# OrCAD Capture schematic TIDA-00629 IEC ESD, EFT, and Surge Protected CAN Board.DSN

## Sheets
1 S01 COVER PAGE: note: 6591689; note: M. PEFFERS; note: KRYPTON SOLUTIONS
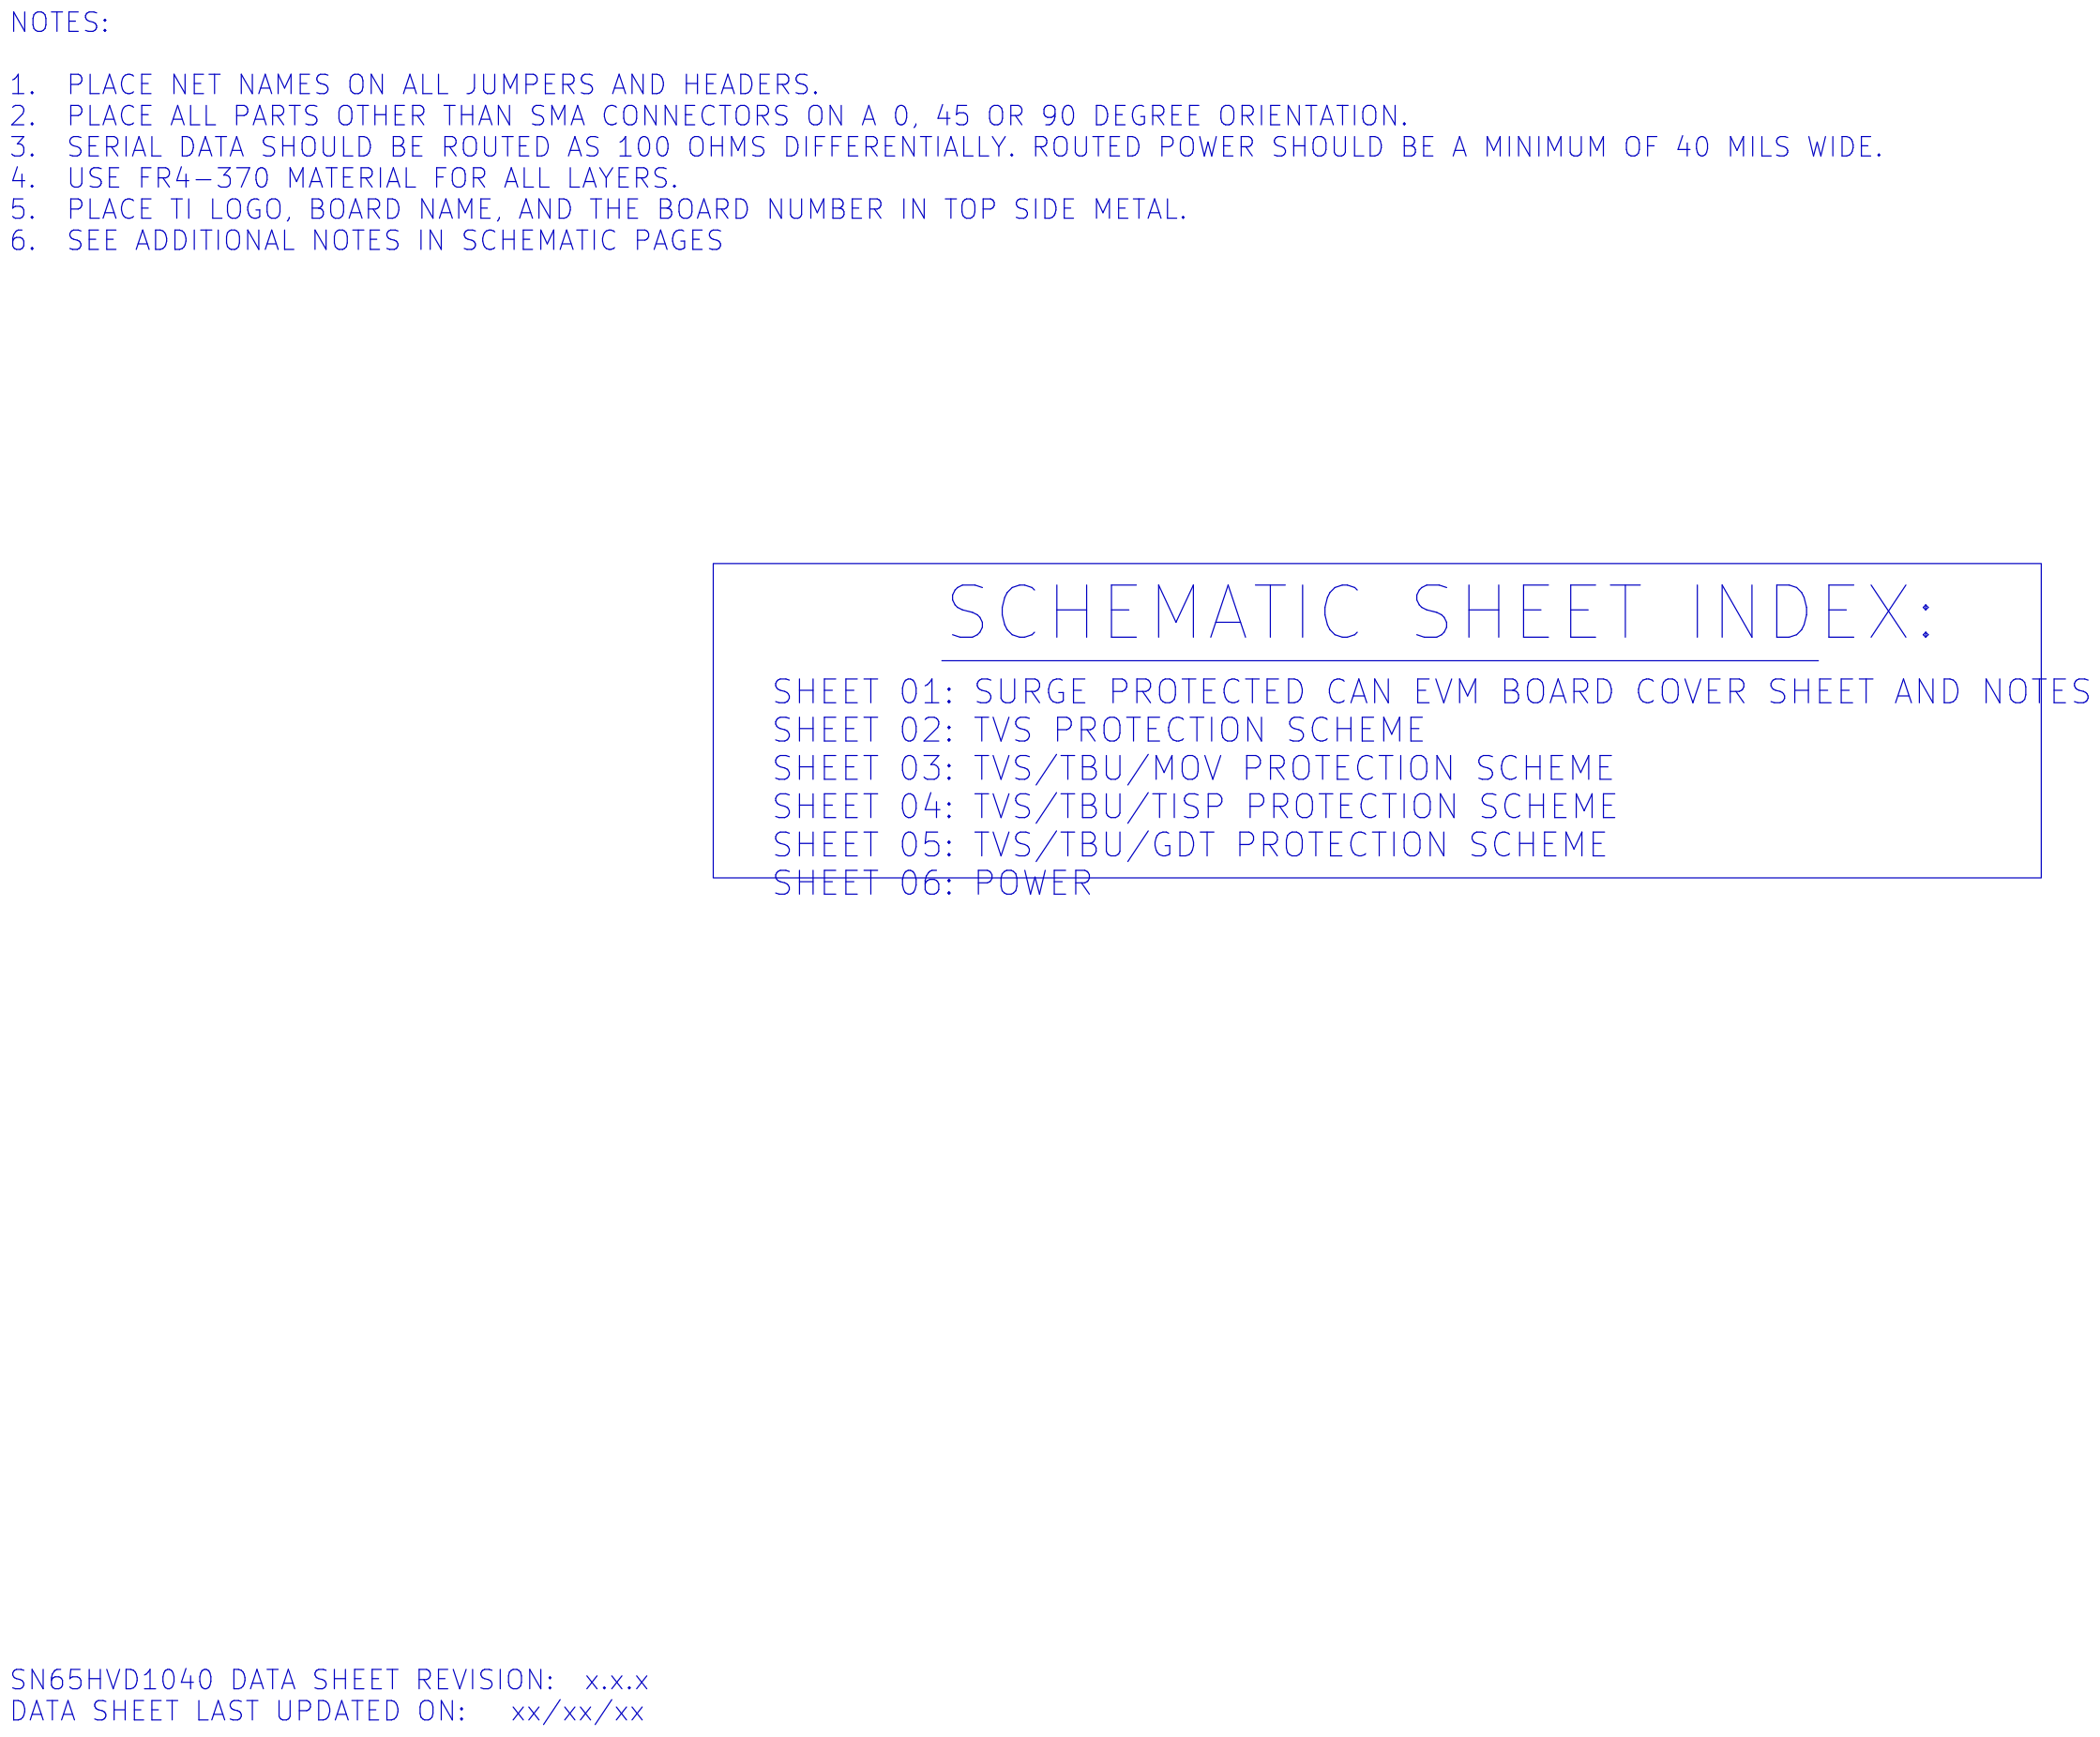
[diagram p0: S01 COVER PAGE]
2 S02 TVS PROTECTION: size B
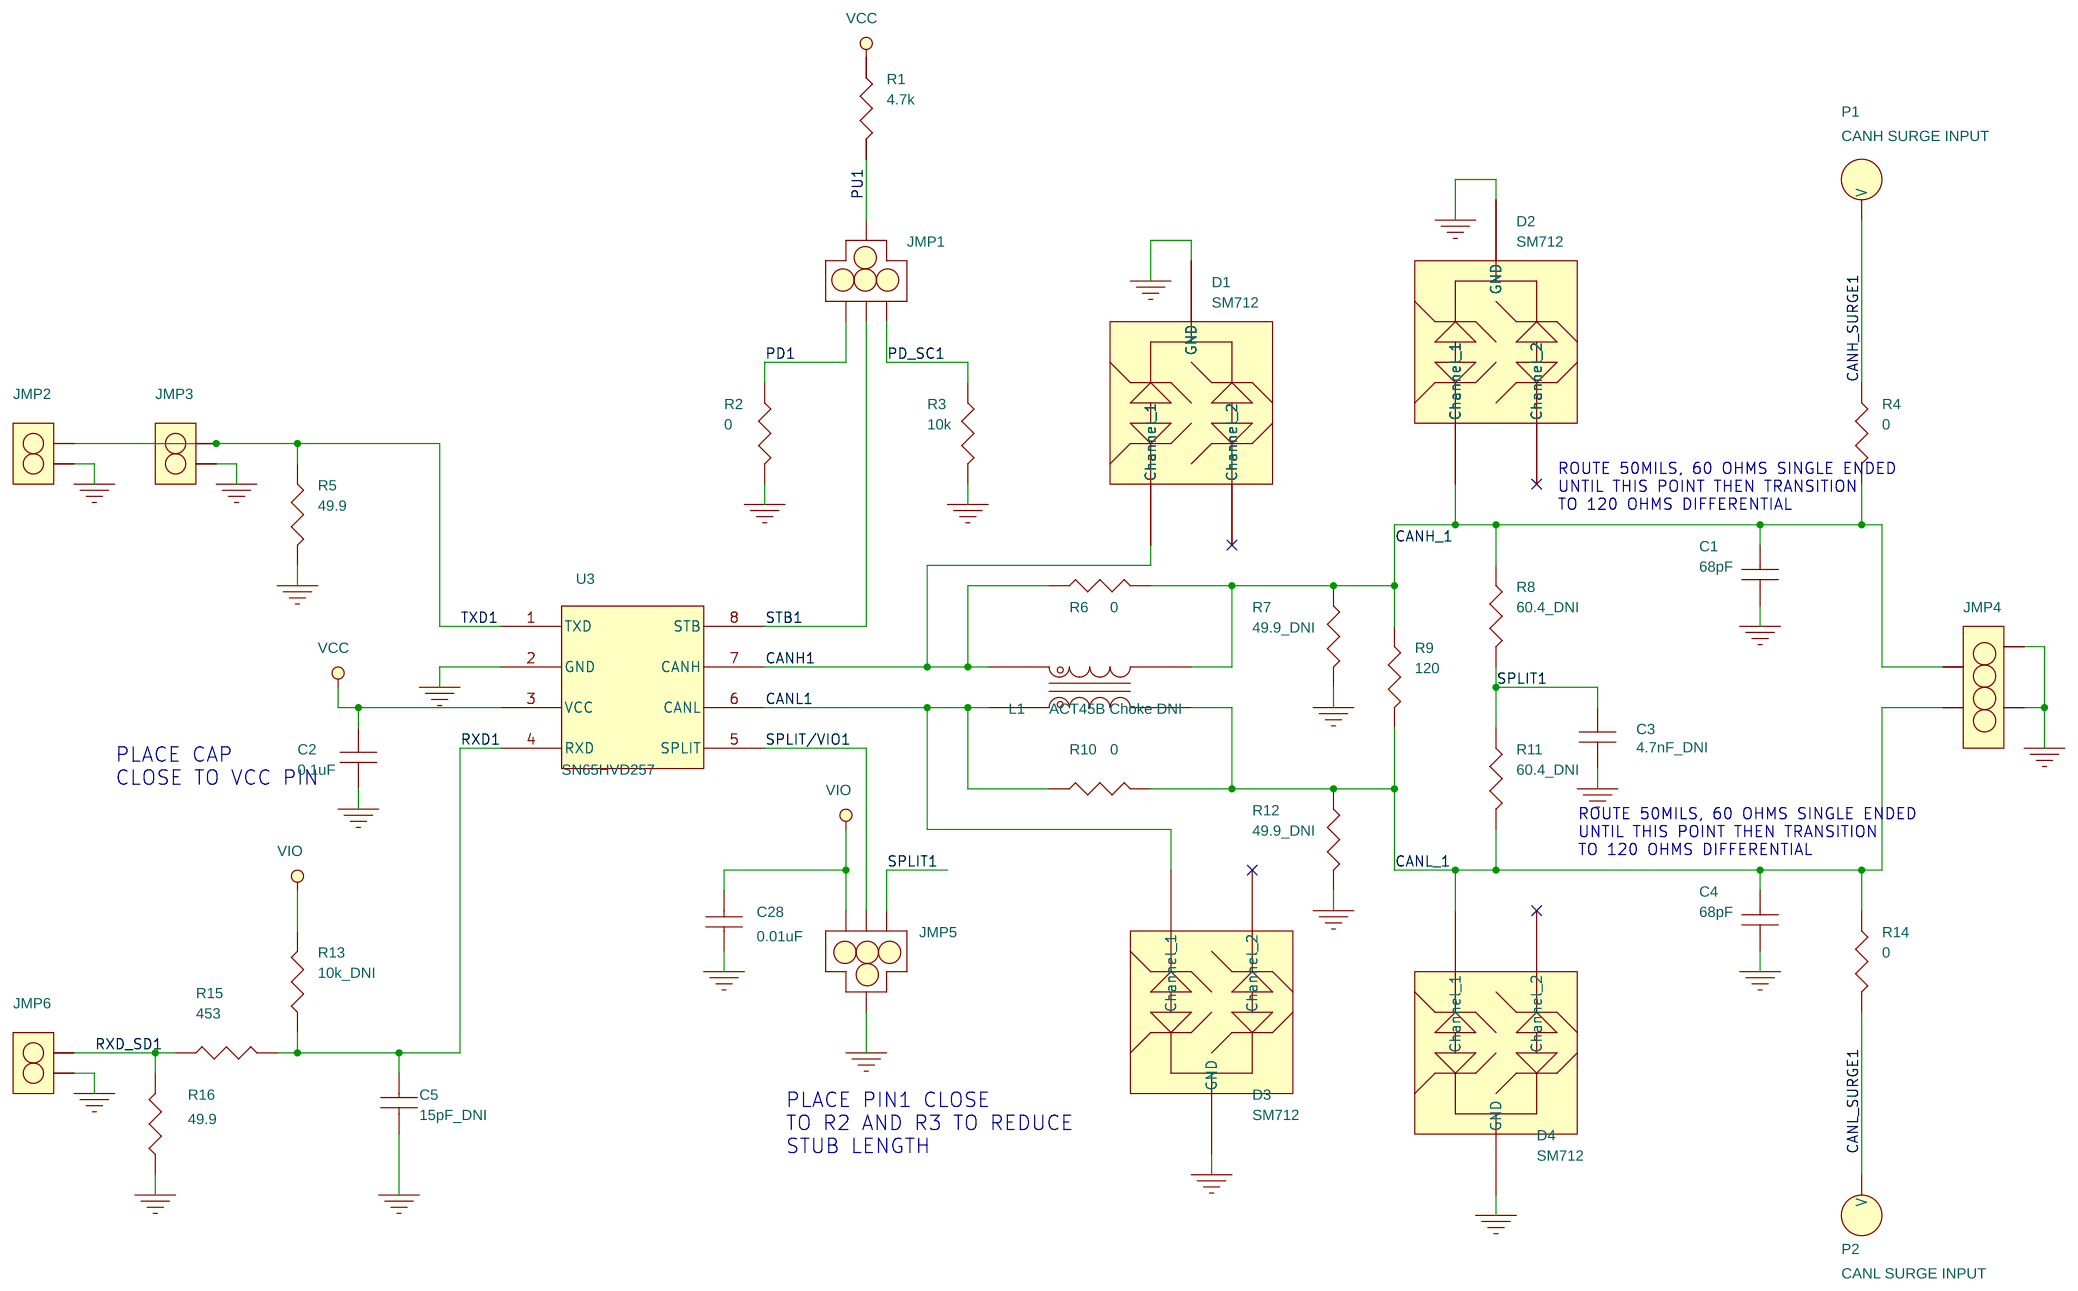
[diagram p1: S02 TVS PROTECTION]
3 S03 TVS, TBU, MOV PROTECTION: size B
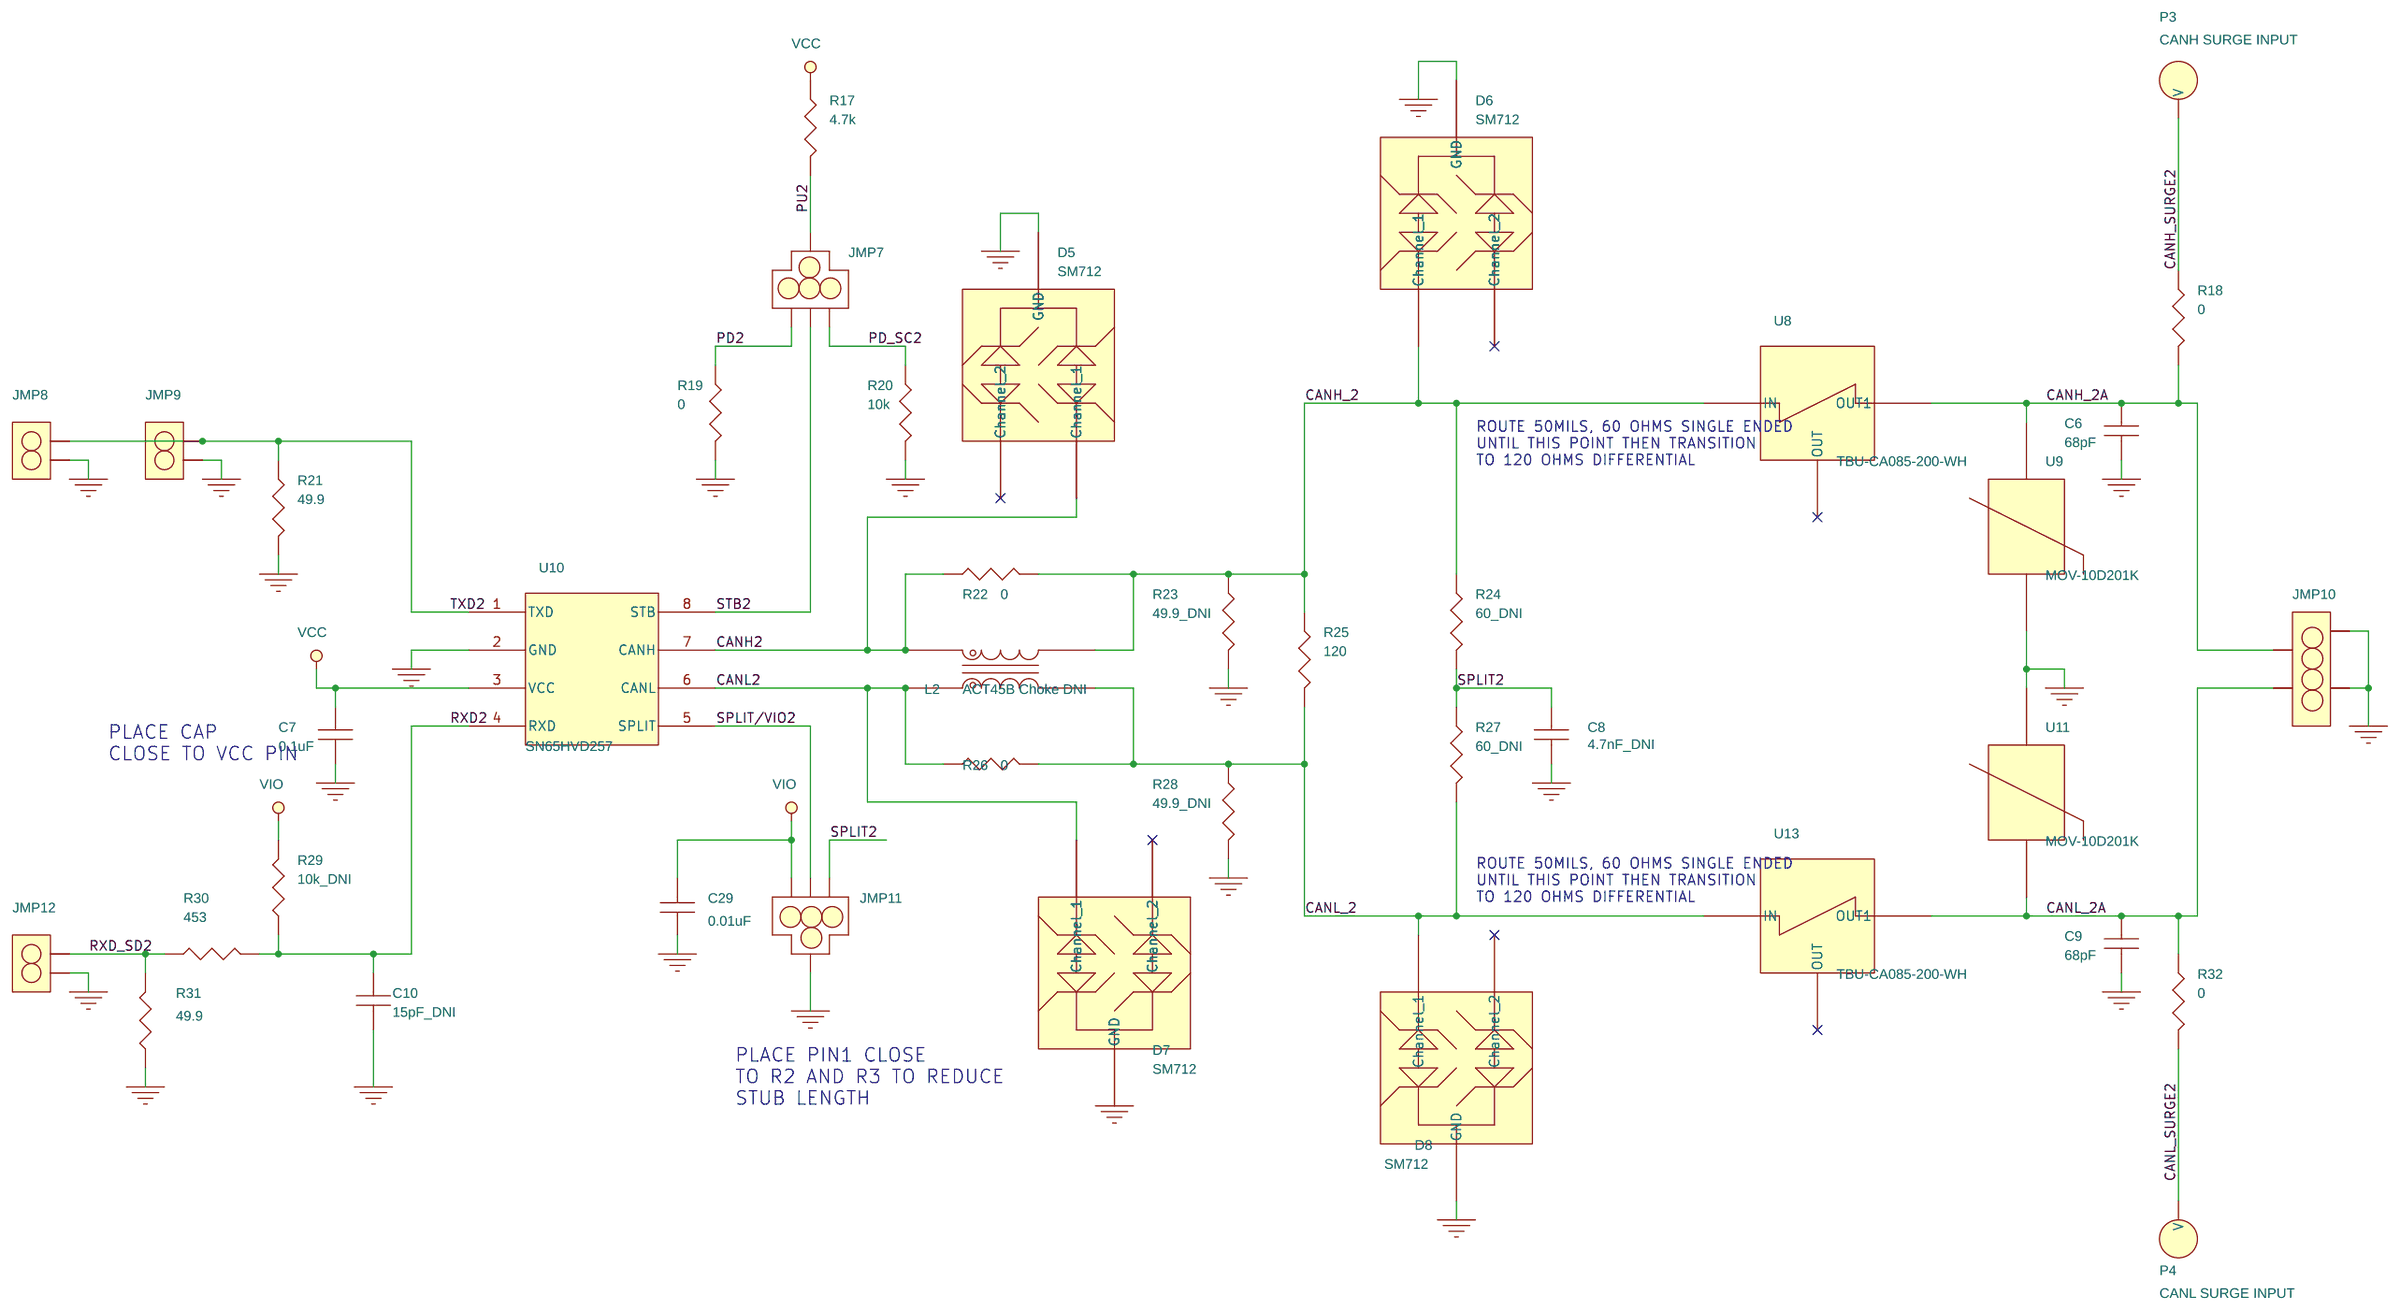
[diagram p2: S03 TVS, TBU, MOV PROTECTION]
4 S04 TVS, TBU, TISP PROTECTION: size B
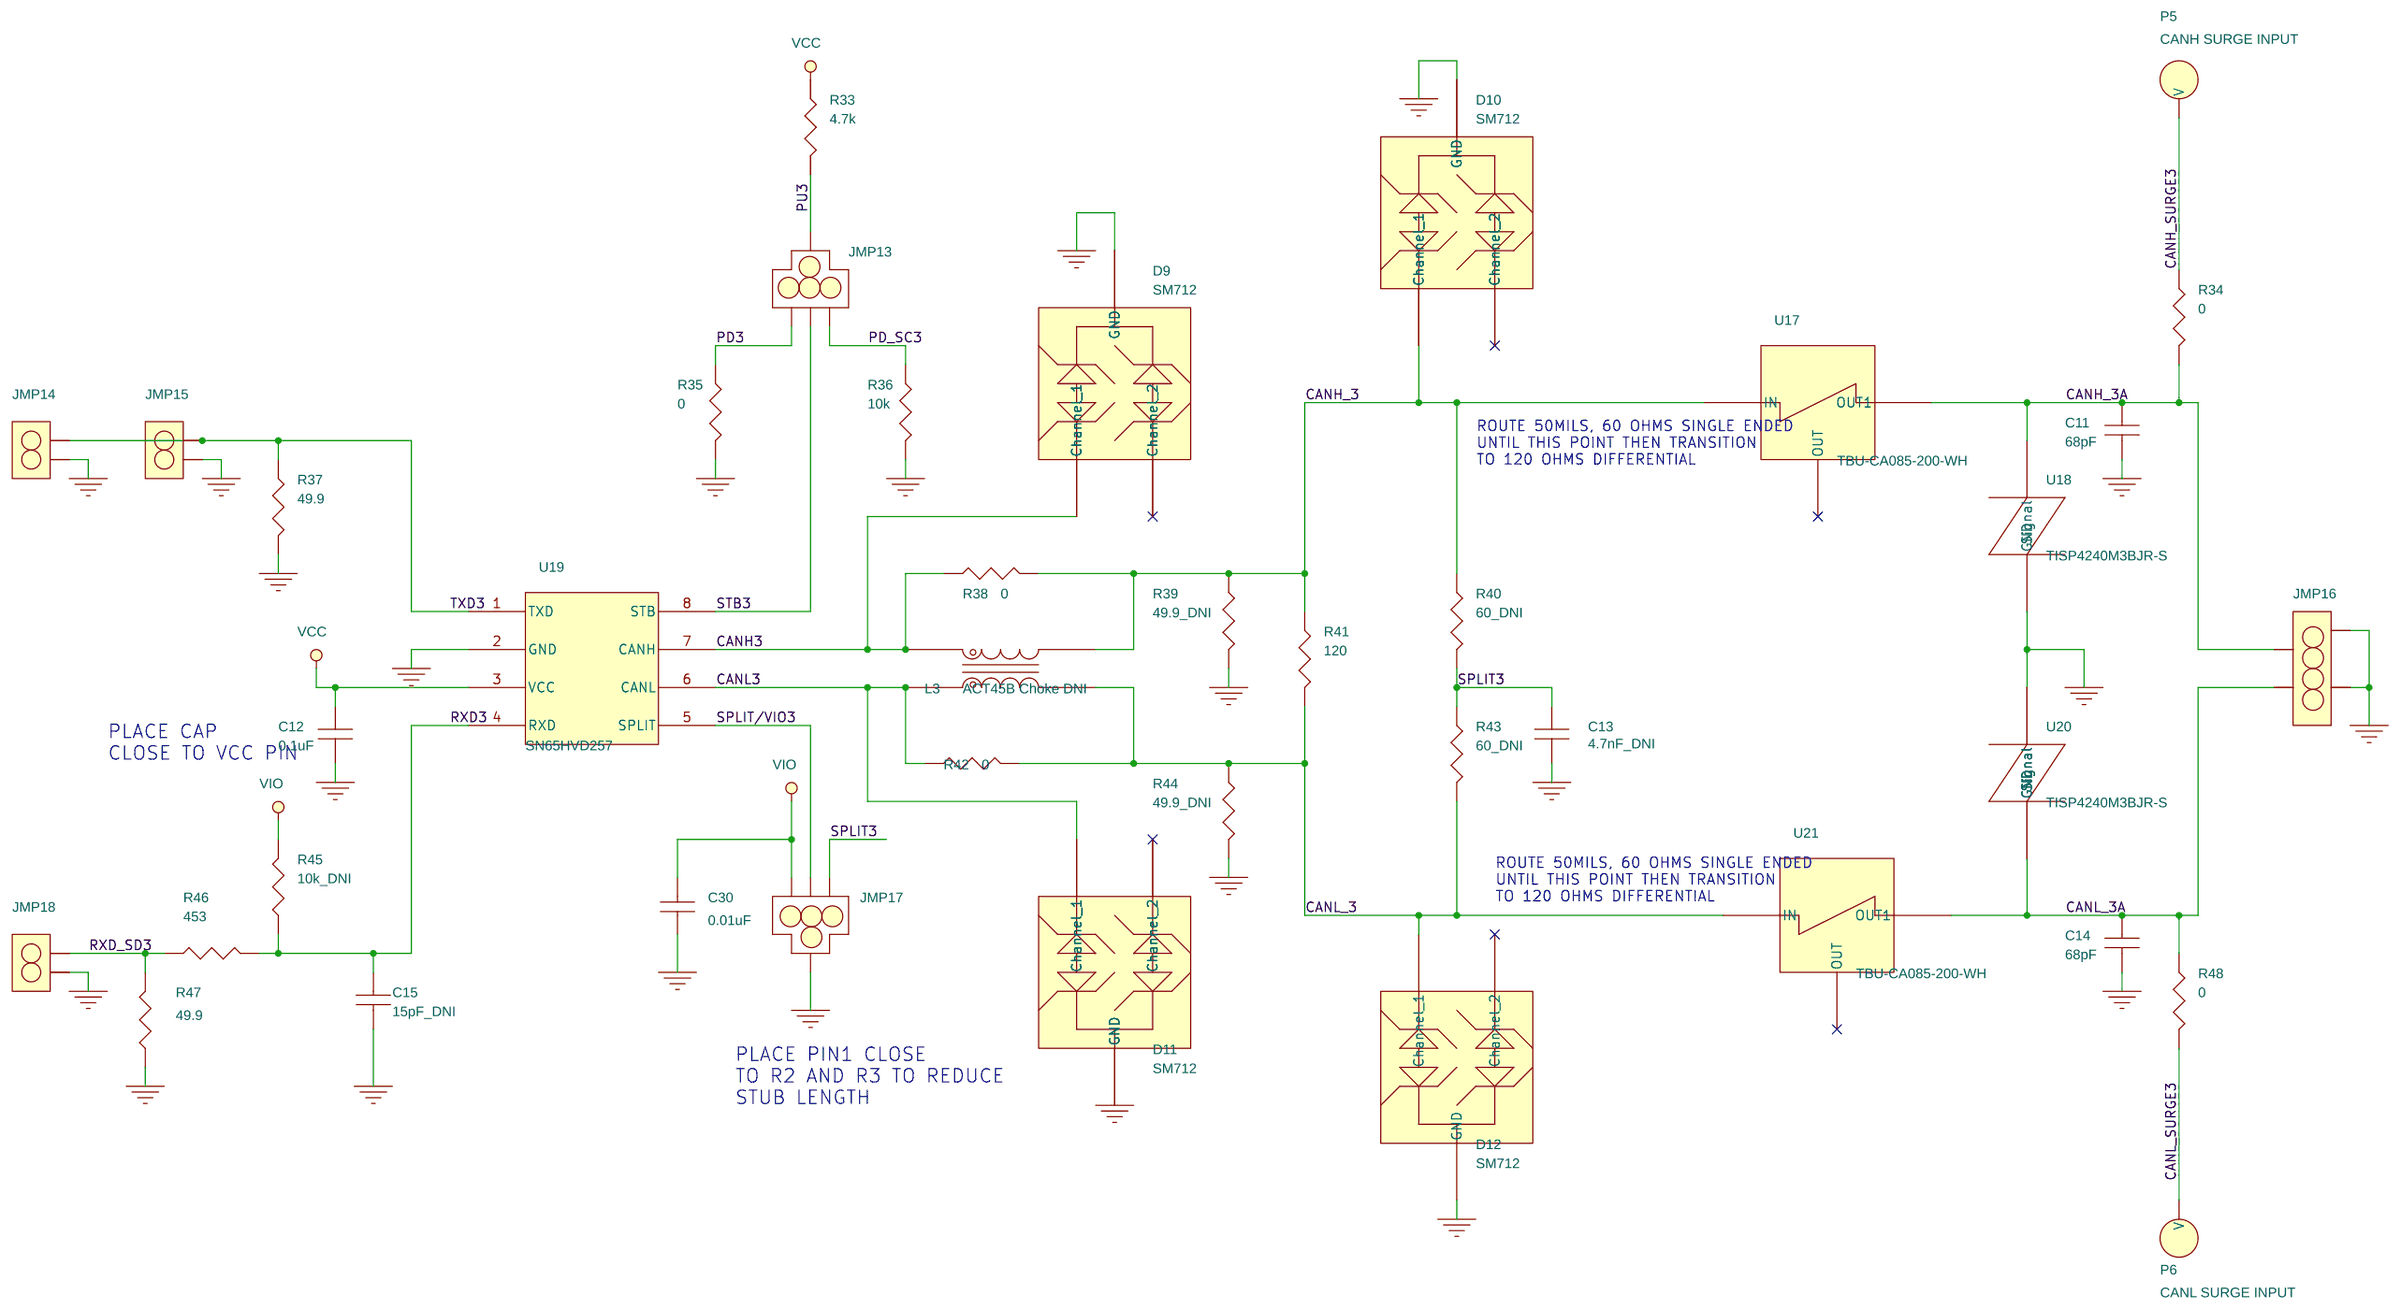
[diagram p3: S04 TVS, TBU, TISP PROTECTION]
5 S05 TVS, TBU, GDT PROTECTION: size B
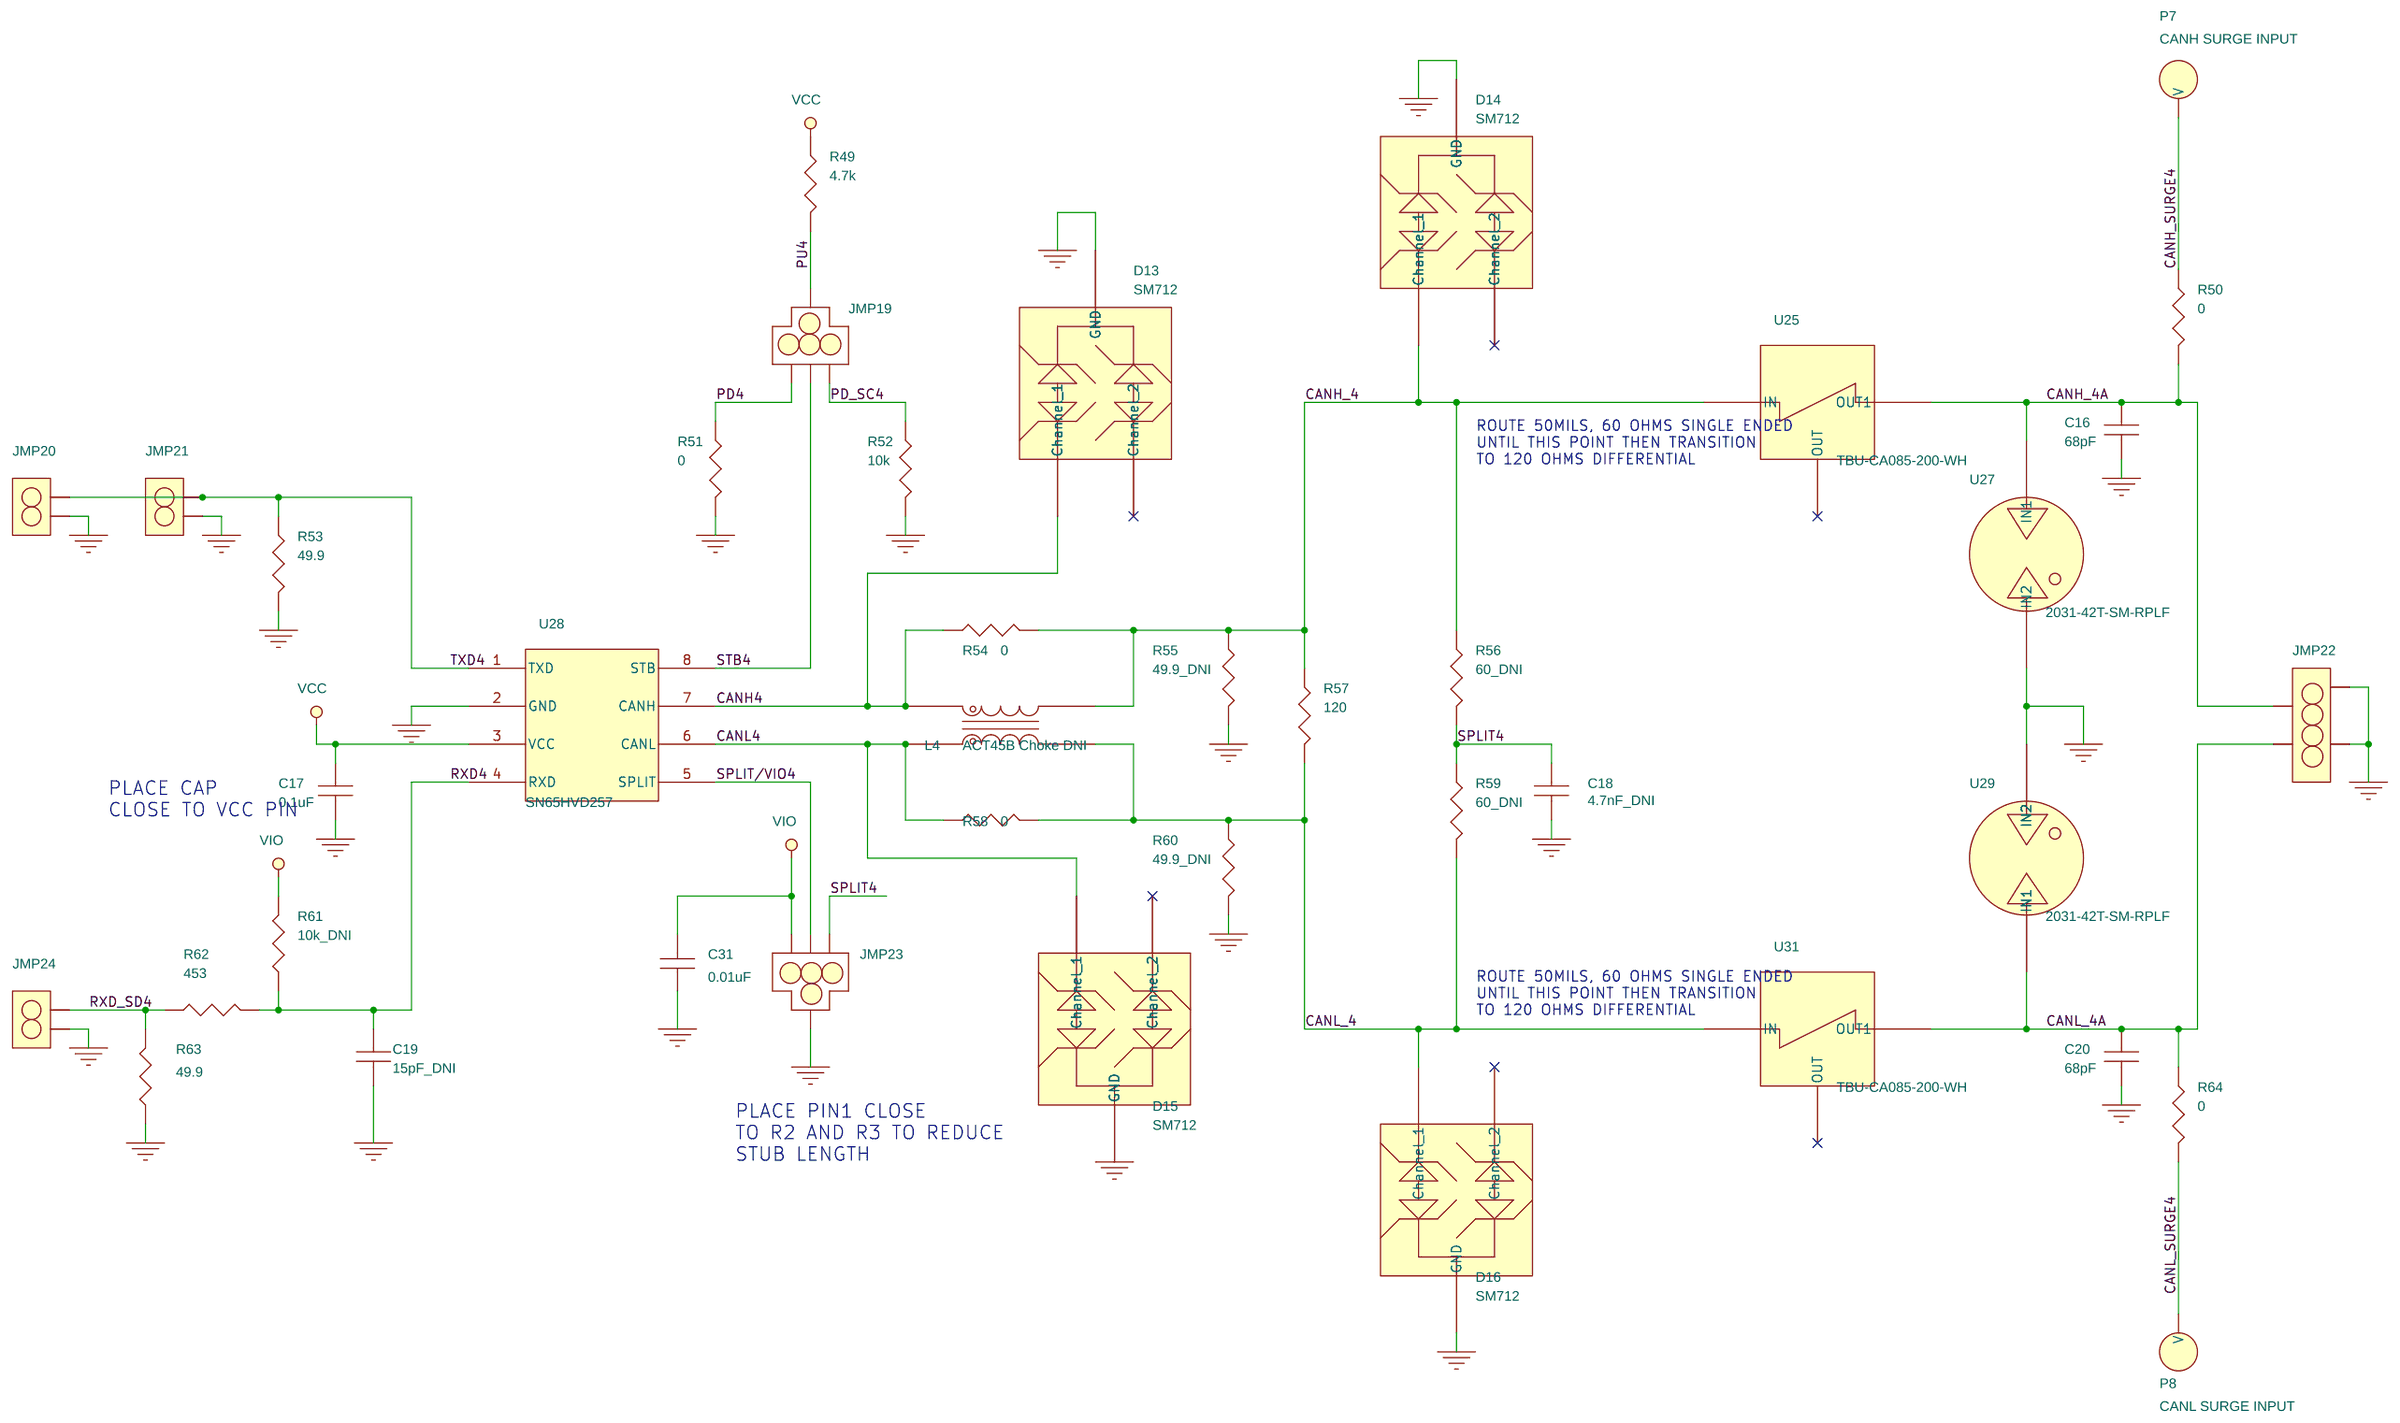
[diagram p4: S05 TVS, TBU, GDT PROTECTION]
6 S06 POWER: size B
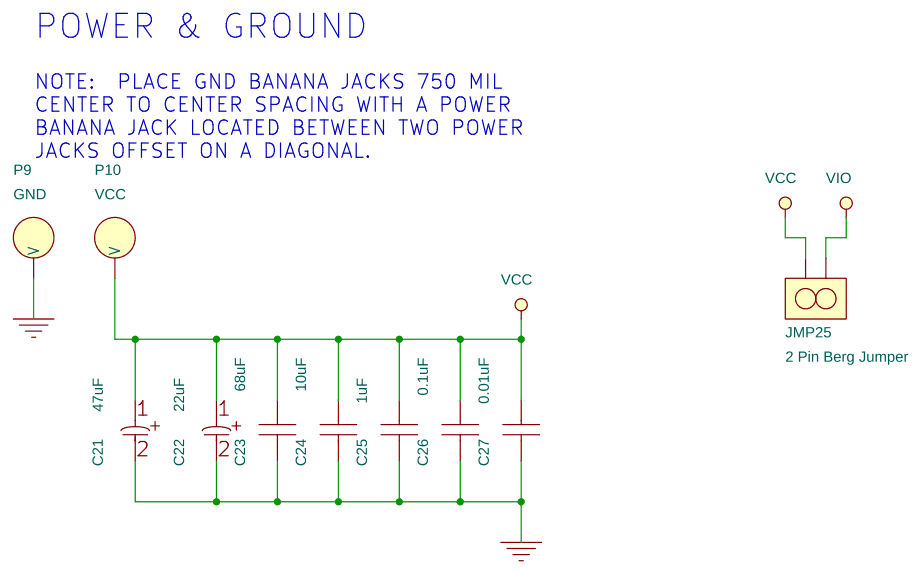
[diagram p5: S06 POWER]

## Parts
sheet S02 TVS PROTECTION
C1  68pF  [0603]
C2  0.1uF  [0402]
C3  4.7nF_DNI  [0402]
C4  68pF  [0603]
C5  15pF_DNI  [0402]
C28  0.01uF  [0603]
D1  SM712  [SOT23]
D2  SM712  [SOT23]
D3  SM712  [SOT23]
D4  SM712  [SOT23]
JMP1  -  [berg2x3tee]
JMP2  -  [HDR_THVT_1x2_100]
JMP3  -  [HDR_THVT_1x2_100]
JMP4  -  [HDR_THVT_1x4_100]
JMP5  -  [berg2x3tee]
JMP6  -  [HDR_THVT_1x2_100]
L1  ACT45B Choke DNI  [IND_ACT45B_SMT_4p5x3p2mm]
P1  CANH SURGE INPUT  [JACK_THVT_BANANA_500dia]
P2  CANL SURGE INPUT  [JACK_THVT_BANANA_500dia]
R1  4.7k  [0603]
R2  0  [0603]
R3  10k  [0603]
R4  0  [0805]
R5  49.9  [0603]
R6  0  [0603]
R7  49.9_DNI  [0603]
R8  60.4_DNI  [0603]
R9  120  [0603]
R10  0  [0603]
R11  60.4_DNI  [0603]
R12  49.9_DNI  [0603]
R13  10k_DNI  [0603]
R14  0  [0805]
R15  453  [0603]
R16  49.9  [0603]
U3  SN65HVD257  [soic8_157x197_50]
sheet S03 TVS, TBU, MOV PROTECTION
C6  68pF  [0603]
C7  0.1uF  [0402]
C8  4.7nF_DNI  [0402]
C9  68pF  [0603]
C10  15pF_DNI  [0402]
C29  0.01uF  [0603]
D5  SM712  [SOT23]
D6  SM712  [SOT23]
D7  SM712  [SOT23]
D8  SM712  [SOT23]
JMP7  -  [berg2x3tee]
JMP8  -  [HDR_THVT_1x2_100]
JMP9  -  [HDR_THVT_1x2_100]
JMP10  -  [HDR_THVT_1x4_100]
JMP11  -  [berg2x3tee]
JMP12  -  [HDR_THVT_1x2_100]
L2  ACT45B Choke DNI  [IND_ACT45B_SMT_4p5x3p2mm]
P3  CANH SURGE INPUT  [JACK_THVT_BANANA_500dia]
P4  CANL SURGE INPUT  [JACK_THVT_BANANA_500dia]
R17  4.7k  [0603]
R18  0  [0805]
R19  0  [0603]
R20  10k  [0603]
R21  49.9  [0603]
R22  0  [0603]
R23  49.9_DNI  [0603]
R24  60_DNI  [0603]
R25  120  [0603]
R26  0  [0603]
R27  60_DNI  [0603]
R28  49.9_DNI  [0603]
R29  10k_DNI  [0603]
R30  453  [0603]
R31  49.9  [0603]
R32  0  [0805]
U8  TBU-CA085-200-WH  [DFN_3_157X256]
U9  MOV-10D201K  [VAR_DISC_3p8x12p5mm]
U10  SN65HVD257  [soic8_157x197_50]
U11  MOV-10D201K  [VAR_DISC_3p8x12p5mm]
U13  TBU-CA085-200-WH  [DFN_3_157X256]
sheet S04 TVS, TBU, TISP PROTECTION
C11  68pF  [0603]
C12  0.1uF  [0402]
C13  4.7nF_DNI  [0402]
C14  68pF  [0603]
C15  15pF_DNI  [0402]
C30  0.01uF  [0603]
D9  SM712  [SOT23]
D10  SM712  [SOT23]
D11  SM712  [SOT23]
D12  SM712  [SOT23]
JMP13  -  [berg2x3tee]
JMP14  -  [HDR_THVT_1x2_100]
JMP15  -  [HDR_THVT_1x2_100]
JMP16  -  [HDR_THVT_1x4_100]
JMP17  -  [berg2x3tee]
JMP18  -  [HDR_THVT_1x2_100]
L3  ACT45B Choke DNI  [IND_ACT45B_SMT_4p5x3p2mm]
P5  CANH SURGE INPUT  [JACK_THVT_BANANA_500dia]
P6  CANL SURGE INPUT  [JACK_THVT_BANANA_500dia]
R33  4.7k  [0603]
R34  0  [0805]
R35  0  [0603]
R36  10k  [0603]
R37  49.9  [0603]
R38  0  [0603]
R39  49.9_DNI  [0603]
R40  60_DNI  [0603]
R41  120  [0603]
R42  0  [0603]
R43  60_DNI  [0603]
R44  49.9_DNI  [0603]
R45  10k_DNI  [0603]
R46  453  [0603]
R47  49.9  [0603]
R48  0  [0805]
U17  TBU-CA085-200-WH  [DFN_3_157X256]
U18  TISP4240M3BJR-S  [do-214aa]
U19  SN65HVD257  [soic8_157x197_50]
U20  TISP4240M3BJR-S  [do-214aa]
U21  TBU-CA085-200-WH  [DFN_3_157X256]
sheet S05 TVS, TBU, GDT PROTECTION
C16  68pF  [0603]
C17  0.1uF  [0402]
C18  4.7nF_DNI  [0402]
C19  15pF_DNI  [0402]
C20  68pF  [0603]
C31  0.01uF  [0603]
D13  SM712  [SOT23]
D14  SM712  [SOT23]
D15  SM712  [SOT23]
D16  SM712  [SOT23]
JMP19  -  [berg2x3tee]
JMP20  -  [HDR_THVT_1x2_100]
JMP21  -  [HDR_THVT_1x2_100]
JMP22  -  [HDR_THVT_1x4_100]
JMP23  -  [berg2x3tee]
JMP24  -  [HDR_THVT_1x2_100]
L4  ACT45B Choke DNI  [IND_ACT45B_SMT_4p5x3p2mm]
P7  CANH SURGE INPUT  [JACK_THVT_BANANA_500dia]
P8  CANL SURGE INPUT  [JACK_THVT_BANANA_500dia]
R49  4.7k  [0603]
R50  0  [0805]
R51  0  [0603]
R52  10k  [0603]
R53  49.9  [0603]
R54  0  [0603]
R55  49.9_DNI  [0603]
R56  60_DNI  [0603]
R57  120  [0603]
R58  0  [0603]
R59  60_DNI  [0603]
R60  49.9_DNI  [0603]
R61  10k_DNI  [0603]
R62  453  [0603]
R63  49.9  [0603]
R64  0  [0805]
U25  TBU-CA085-200-WH  [DFN_3_157X256]
U27  2031-42T-SM-RPLF  [GDT_SM_2031-xxT]
U28  SN65HVD257  [soic8_157x197_50]
U29  2031-42T-SM-RPLF  [GDT_SM_2031-xxT]
U31  TBU-CA085-200-WH  [DFN_3_157X256]
sheet S06 POWER
C21  47uF  [7343]
C22  22uF  [7343]
C23  68uF  [1210]
C24  10uF  [0805]
C25  1uF  [1206]
C26  0.1uF  [1206]
C27  0.01uF  [0805]
JMP25  2 Pin Berg Jumper  [HDR_THVT_1x2_100]
P9  GND  [JACK_THVT_BANANA_500dia]
P10  VCC  [JACK_THVT_BANANA_500dia]

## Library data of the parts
C1 C4 C6 C9 C11 C14 C16 C20 = CAP_NP
C2 C3 C5 C7 C8 C10 C12 C13 C15 C17-C19 C28-C31 = cc0402
D1-D16 = SM712
JMP1 JMP5 JMP7 JMP11 JMP13 JMP17 JMP19 JMP23 = 4_Pin-T_Berg_Jumper
JMP2 JMP3 JMP6 JMP8 JMP9 JMP12 JMP14 JMP15 JMP18 JMP20 JMP21 JMP24 JMP25 = 2_Pin_Berg_Jumper
JMP4 JMP10 JMP16 JMP22 = 4_Pin_Berg_Jumper_Stagard_Side
L1-L4 = ACT45B_Choke
P1-P10 = Banana-Jack
R1-R64 = r0603
U3 U10 U19 U28 = SN65HVD1040
U8 U13 U17 U21 U25 U31 = TBU-CA085-200-WH_0
U9 U11 = MOV-10D201K
U18 U20 = TISP4240M3BJR-S
U27 U29 = 2031-42T-SM-RPLF
C21 C22 = c7343
C23 C25 = NPCap1206_1.0uf
C24 = CAP_NP: Vendor: Digi-Key
C26 = NPCap1206_0.1uf
C27 = NPCap0805_0.01uf

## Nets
GND: C1.2 C2.2 C3.2 C4.2 C5.2 C6.2 C7.2 C8.2 C9.2 C10.2 C11.2 C12.2 C13.2 C14.2 C15.2 C16.2 C17.2 C18.2 C19.2 C20.2 C21.2 C22.2 C23.2 C24.2 C25.2 C26.2 C27.2 C28.1 C29.1 C30.1 C31.1 D1.3(GND) D2.3(GND) D3.3(GND) D4.3(GND) D5.3(GND) D6.3(GND) D7.3(GND) D8.3(GND) D9.3(GND) D10.3(GND) D11.3(GND) D12.3(GND) D13.3(GND) D14.3(GND) D15.3(GND) D16.3(GND) JMP2.1 JMP3.1 JMP4.1 JMP4.4 JMP5.4 JMP6.1 JMP8.1 JMP9.1 JMP10.1 JMP10.4 JMP11.4 JMP12.1 JMP14.1 JMP15.1 JMP16.1 JMP16.4 JMP17.4 JMP18.1 JMP20.1 JMP21.1 JMP22.1 JMP22.4 JMP23.4 JMP24.1 P9.1(V) R2.2 R3.2 R5.2 R7.2 R12.2 R16.1 R19.2 R20.2 R21.2 R23.2 R28.2 R31.1 R35.2 R36.2 R37.2 R39.2 R44.2 R47.1 R51.2 R52.2 R53.2 R55.2 R60.2 R63.1 U3.2(GND) U9.2 U10.2(GND) U11.1 U18.2(GND) U19.2(GND) U20.1(Signal) U27.2(IN2) U28.2(GND) U29.2(IN2)
VCC: C2.1 C7.1 C12.1 C17.1 C21.1 C22.1 C23.1 C24.1 C25.1 C26.1 C27.1 JMP25.2 P10.1(V) U3.3(VCC) U10.3(VCC) U19.3(VCC) U28.3(VCC)
CANH1: D1.1(Channel) L1.1 R6.1 U3.7(CANH)
CANH2: D5.1(Channel) L2.1 R22.1 U10.7(CANH)
CANH3: D9.1(Channel) L3.1 R38.1 U19.7(CANH)
CANH4: D13.1(Channel) L4.1 R54.1 U28.7(CANH)
CANH_1: C1.1 D2.1(Channel) JMP4.2 L1.4 R4.2 R6.2 R7.1 R8.1 R9.1
CANH_2: D6.1(Channel) L2.4 R22.2 R23.1 R24.1 R25.1 U8.1(IN)
CANH_2A: C6.1 JMP10.2 R18.2 U8.3(OUT1) U9.1
CANH_3: D10.1(Channel) L3.4 R38.2 R39.1 R40.1 R41.1 U17.1(IN)
CANH_3A: C11.1 JMP16.2 R34.2 U17.3(OUT1) U18.1(Signal)
CANH_4: D14.1(Channel) L4.4 R54.2 R55.1 R56.1 R57.1 U25.1(IN)
CANH_4A: C16.1 JMP22.2 R50.2 U25.3(OUT1) U27.1(IN1)
CANH_SURGE1: P1.1(V) R4.1
CANH_SURGE2: P3.1(V) R18.1
CANH_SURGE3: P5.1(V) R34.1
CANH_SURGE4: P7.1(V) R50.1
CANL1: D3.1(Channel) L1.2 R10.1 U3.6(CANL)
CANL2: D7.1(Channel) L2.2 R26.1 U10.6(CANL)
CANL3: D11.1(Channel) L3.2 R42.1 U19.6(CANL)
CANL4: D15.1(Channel) L4.2 R58.1 U28.6(CANL)
CANL_1: C4.1 D4.1(Channel) JMP4.3 L1.3 R9.2 R10.2 R11.2 R12.1 R14.1
CANL_2: D8.1(Channel) L2.3 R25.2 R26.2 R27.2 R28.1 U13.1(IN)
CANL_2A: C9.1 JMP10.3 R32.1 U11.2 U13.3(OUT1)
CANL_3: D12.1(Channel) L3.3 R41.2 R42.2 R43.2 R44.1 U21.1(IN)
CANL_3A: C14.1 JMP16.3 R48.1 U20.2(GND) U21.3(OUT1)
CANL_4: D16.1(Channel) L4.3 R57.2 R58.2 R59.2 R60.1 U31.1(IN)
CANL_4A: C20.1 JMP22.3 R64.1 U29.1(IN1) U31.3(OUT1)
CANL_SURGE1: P2.1(V) R14.2
CANL_SURGE2: P4.1(V) R32.2
CANL_SURGE3: P6.1(V) R48.2
CANL_SURGE4: P8.1(V) R64.2
PD1: JMP1.1 R2.1
PD2: JMP7.1 R19.1
PD3: JMP13.1 R35.1
PD4: JMP19.1 R51.1
PD_SC1: JMP1.3 R3.1
PD_SC2: JMP7.3 R20.1
PD_SC3: JMP13.3 R36.1
PD_SC4: JMP19.3 R52.1
PU1: JMP1.4 R1.2
PU2: JMP7.4 R17.2
PU3: JMP13.4 R33.2
PU4: JMP19.4 R49.2
RXD1: C5.1 R13.1 R15.2 U3.4(RXD)
RXD2: C10.1 R29.1 R30.2 U10.4(RXD)
RXD3: C15.1 R45.1 R46.2 U19.4(RXD)
RXD4: C19.1 R61.1 R62.2 U28.4(RXD)
RXD_SD1: JMP6.2 R15.1 R16.2
RXD_SD2: JMP12.2 R30.1 R31.2
RXD_SD3: JMP18.2 R46.1 R47.2
RXD_SD4: JMP24.2 R62.1 R63.2
SPLIT1: C3.1 JMP5.1 R8.2 R11.1
SPLIT2: C8.1 JMP11.1 R24.2 R27.1
SPLIT3: C13.1 JMP17.1 R40.2 R43.1
SPLIT4: C18.1 JMP23.1 R56.2 R59.1
SPLIT/VIO1: JMP5.2 U3.5(SPLIT)
SPLIT/VIO2: JMP11.2 U10.5(SPLIT)
SPLIT/VIO3: JMP17.2 U19.5(SPLIT)
SPLIT/VIO4: JMP23.2 U28.5(SPLIT)
STB1: JMP1.2 U3.8(STB)
STB2: JMP7.2 U10.8(STB)
STB3: JMP13.2 U19.8(STB)
STB4: JMP19.2 U28.8(STB)
TXD1: JMP2.2 JMP3.2 R5.1 U3.1(TXD)
TXD2: JMP8.2 JMP9.2 R21.1 U10.1(TXD)
TXD3: JMP14.2 JMP15.2 R37.1 U19.1(TXD)
TXD4: JMP20.2 JMP21.2 R53.1 U28.1(TXD)
VIO: C28.2 C29.2 C30.2 C31.2 JMP5.3 JMP11.3 JMP17.3 JMP23.3 JMP25.1 R1.1 R13.2 R17.1 R29.2 R33.1 R45.2 R49.1 R61.2

Not connected (* = marked no-connect by the designer): D1 2(Channel)*; D2 2(Channel)*; D3 2(Channel)*; D4 2(Channel)*; D5 2(Channel)*; D6 2(Channel)*; D7 2(Channel)*; D8 2(Channel)*; D9 2(Channel)*; D10 2(Channel)*; D11 2(Channel)*; D12 2(Channel)*; D13 2(Channel)*; D14 2(Channel)*; D15 2(Channel)*; D16 2(Channel)*; U8 2(OUT)*; U13 2(OUT)*; U17 2(OUT)*; U21 2(OUT)*; U25 2(OUT)*; U31 2(OUT)*

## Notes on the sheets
sheet 1
- NOTES:
  1.  PLACE NET NAMES ON ALL JUMPERS AND HEADERS.
  2.  PLACE ALL PARTS OTHER THAN SMA CONNECTORS ON A 0, 45 OR 90 DEGREE ORIENTATION.
  3.  SERIAL DATA SHOULD BE ROUTED AS 100 OHMS DIFFERENTIALLY. ROUTED POWER SHOULD BE A MINIMUM OF 40 MILS WIDE.
  4.  USE FR4-370 MATERIAL FOR ALL LAYERS.
  5.  PLACE TI LOGO, BOARD NAME, AND THE BOARD NUMBER IN TOP SIDE METAL.
  6.  SEE ADDITIONAL NOTES IN SCHEMATIC PAGES
- SCHEMATIC SHEET INDEX:
- SHEET 01: SURGE PROTECTED CAN EVM BOARD COVER SHEET AND NOTES
  SHEET 02: TVS PROTECTION SCHEME
  SHEET 03: TVS/TBU/MOV PROTECTION SCHEME
  SHEET 04: TVS/TBU/TISP PROTECTION SCHEME
  SHEET 05: TVS/TBU/GDT PROTECTION SCHEME
  SHEET 06: POWER
- SN65HVD1040 DATA SHEET REVISION:  x.x.x
  DATA SHEET LAST UPDATED ON:   xx/xx/xx
sheet 2
- ROUTE 50MILS, 60 OHMS SINGLE ENDED
  UNTIL THIS POINT THEN TRANSITION
  TO 120 OHMS DIFFERENTIAL
- PLACE CAP
  CLOSE TO VCC PIN
- ROUTE 50MILS, 60 OHMS SINGLE ENDED
  UNTIL THIS POINT THEN TRANSITION
  TO 120 OHMS DIFFERENTIAL
- PLACE PIN1 CLOSE
  TO R2 AND R3 TO REDUCE
  STUB LENGTH
sheet 3
- ROUTE 50MILS, 60 OHMS SINGLE ENDED
  UNTIL THIS POINT THEN TRANSITION
  TO 120 OHMS DIFFERENTIAL
- PLACE CAP
  CLOSE TO VCC PIN
- ROUTE 50MILS, 60 OHMS SINGLE ENDED
  UNTIL THIS POINT THEN TRANSITION
  TO 120 OHMS DIFFERENTIAL
- PLACE PIN1 CLOSE
  TO R2 AND R3 TO REDUCE
  STUB LENGTH
sheet 4
- ROUTE 50MILS, 60 OHMS SINGLE ENDED
  UNTIL THIS POINT THEN TRANSITION
  TO 120 OHMS DIFFERENTIAL
- PLACE CAP
  CLOSE TO VCC PIN
- ROUTE 50MILS, 60 OHMS SINGLE ENDED
  UNTIL THIS POINT THEN TRANSITION
  TO 120 OHMS DIFFERENTIAL
- PLACE PIN1 CLOSE
  TO R2 AND R3 TO REDUCE
  STUB LENGTH
sheet 5
- ROUTE 50MILS, 60 OHMS SINGLE ENDED
  UNTIL THIS POINT THEN TRANSITION
  TO 120 OHMS DIFFERENTIAL
- PLACE CAP
  CLOSE TO VCC PIN
- ROUTE 50MILS, 60 OHMS SINGLE ENDED
  UNTIL THIS POINT THEN TRANSITION
  TO 120 OHMS DIFFERENTIAL
- PLACE PIN1 CLOSE
  TO R2 AND R3 TO REDUCE
  STUB LENGTH
sheet 6
- POWER & GROUND
- NOTE:  PLACE GND BANANA JACKS 750 MIL
  CENTER TO CENTER SPACING WITH A POWER
  BANANA JACK LOCATED BETWEEN TWO POWER
  JACKS OFFSET ON A DIAGONAL.
